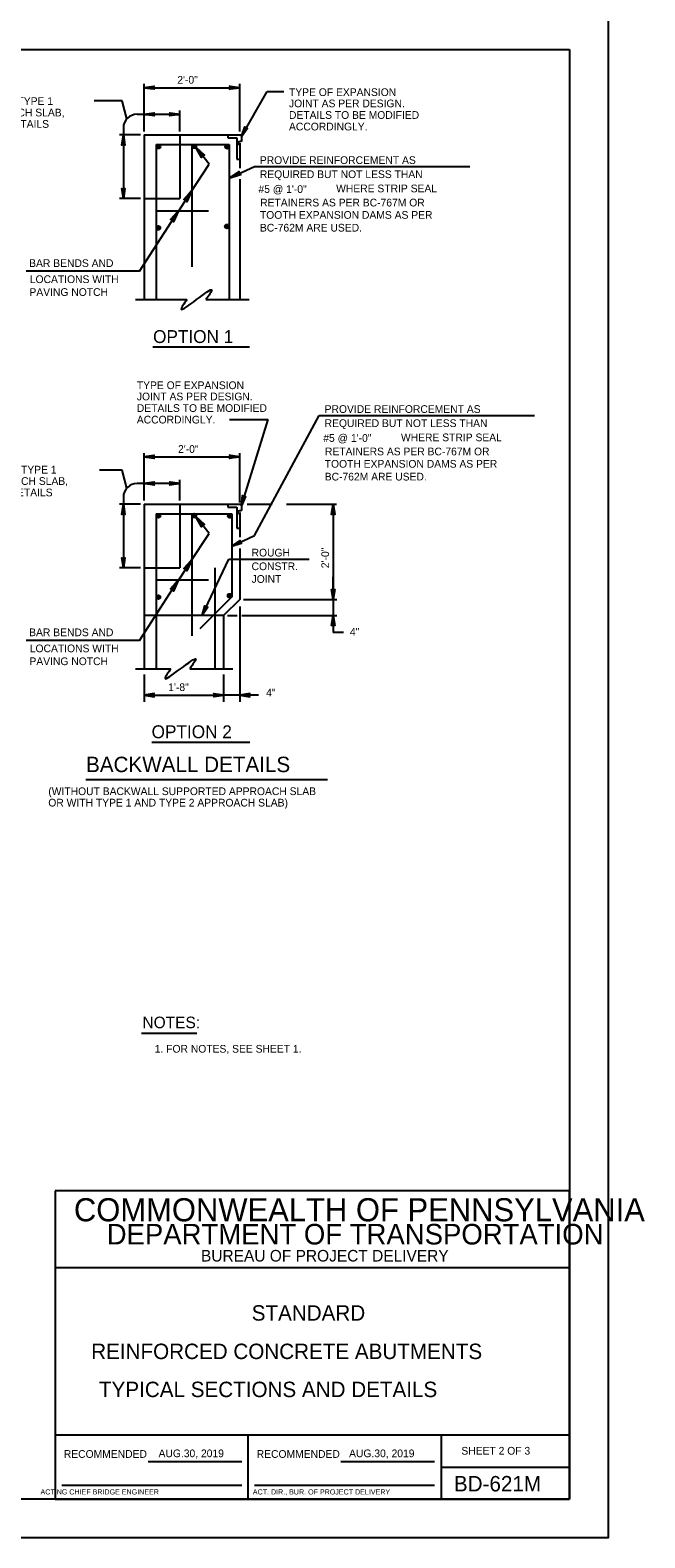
# Model space of a CAD drawing. Extents: x 235 to 2276, y 116 to 1308.
# Drawn here: x 1196 to 1435, y 116 to 703 of the extents above; entities that cross this region are included whole.
import ezdxf

# ---------------------------------------------------------------- set-up
doc = ezdxf.new("R2010")
doc.units = 0
doc.layers.add('1', color=7, linetype='Continuous')
doc.layers.add('PLT-BNDY', color=7, linetype='Continuous')

msp = doc.modelspace()

# ---------------------------------------------------------------- linework, layer by layer
at = {"layer": '1'}
for p, q in [((619.42, 695.41), (1405.42, 695.41)), ((1405.42, 695.41), (1405.42, 131.41)), ((1240.02, 663.53), (1240.02, 682.03)), ((1240.02, 680.53), (1277.14, 680.53)), ((1277.14, 663.53), (1277.14, 682.03)), ((1231.39, 675.4), (1220.58, 675.4)), ((1233.27, 668.4), (1231.39, 675.4)), ((1277.77, 661.53), (1287.77, 679.04)), ((1287.77, 679.04), (1294.23, 679.04)), ((1240.52, 670.15), (1237.27, 670.15)), ((1253.89, 670.15), (1240.02, 670.15)), ((1253.89, 663.53), (1253.89, 671.65)), ((1231.89, 664.9), (1231.89, 660.53)), ((1238.52, 662.15), (1230.39, 662.15)), ((1231.89, 662.15), (1231.89, 637.4)), ((1240.02, 662.15), (1240.02, 598.15)), ((1240.02, 662.15), (1277.77, 662.15)), ((1244.64, 658.4), (1244.64, 598.15)), ((1244.64, 658.4), (1273.08, 658.4)), ((1253.89, 662.15), (1253.89, 637.4)), ((1258.52, 658.4), (1258.52, 610.9)), ((1265.27, 650.78), (1259.89, 657.53)), ((1272.52, 662.15), (1272.52, 661.03)), ((1272.52, 661.03), (1276.02, 661.03)), ((1273.08, 658.4), (1273.08, 598.15)), ((1276.02, 661.03), (1276.02, 652.78)), ((1277.14, 658.9), (1277.14, 649.28)), ((1277.77, 662.15), (1277.77, 659.65)), ((1276.02, 652.78), (1277.14, 652.78)), ((1257.89, 639.53), (1265.27, 650.78)), ((1273.08, 645.28), (1282.89, 649.9)), ((1282.89, 649.9), (1366.6, 649.9)), ((1252.77, 631.65), (1258.52, 640.53)), ((1277.14, 644.9), (1277.14, 598.15)), ((1238.52, 637.4), (1230.39, 637.4)), ((1240.02, 637.4), (1253.89, 637.4)), ((1238.14, 609.15), (1253.39, 632.65)), ((1244.64, 632.65), (1265.02, 632.65)), ((1238.14, 609.15), (1194.14, 609.15)), ((1236.64, 598.15), (1256.64, 598.15)), ((1264.02, 598.15), (1280.77, 598.15)), ((1243.32, 579.68), (1280.9, 579.68)), ((1273.14, 551.41), (1288.14, 551.41)), ((1277.77, 517.91), (1288.14, 551.41)), ((1282.89, 506.28), (1308.08, 553.06)), ((1308.08, 553.06), (1391.8, 553.06)), ((1240.02, 519.91), (1240.02, 538.41)), ((1240.02, 536.91), (1277.14, 536.91)), ((1277.14, 519.16), (1277.14, 538.41)), ((1231.39, 531.78), (1222.64, 531.78)), ((1233.27, 524.78), (1231.39, 531.78)), ((1253.89, 519.91), (1253.89, 528.03)), ((1240.52, 526.53), (1237.27, 526.53)), ((1253.89, 526.53), (1240.02, 526.53)), ((1238.52, 518.53), (1230.39, 518.53)), ((1231.89, 521.28), (1231.89, 516.91)), ((1231.89, 518.53), (1231.89, 493.78)), ((1240.02, 518.53), (1240.02, 454.53)), ((1240.02, 518.53), (1277.77, 518.53)), ((1253.89, 518.53), (1253.89, 493.78)), ((1272.52, 518.53), (1272.52, 517.41)), ((1272.52, 517.41), (1276.02, 517.41)), ((1276.02, 517.41), (1276.02, 509.16)), ((1277.77, 518.53), (1277.77, 516.03)), ((1280.02, 518.53), (1289.77, 518.53)), ((1295.27, 518.53), (1314.77, 518.53)), ((1313.52, 518.53), (1313.52, 481.41)), ((1244.64, 514.78), (1244.64, 454.53)), ((1244.64, 514.78), (1274.14, 514.78)), ((1258.52, 514.78), (1258.52, 467.28)), ((1265.27, 507.16), (1259.89, 513.91)), ((1274.14, 514.78), (1274.14, 482.53)), ((1277.14, 515.28), (1277.14, 505.66)), ((1257.89, 495.91), (1265.27, 507.16)), ((1274.14, 502.16), (1282.89, 506.28)), ((1276.02, 509.16), (1277.14, 509.16)), ((1277.14, 501.28), (1277.14, 481.41)), ((1238.52, 493.78), (1230.39, 493.78)), ((1240.02, 493.78), (1253.89, 493.78)), ((1252.77, 488.03), (1258.52, 496.91)), ((1262.52, 475.16), (1272.89, 497.16)), ((1267.52, 493.78), (1267.52, 454.53)), ((1272.89, 497.16), (1304.14, 497.16)), ((1238.14, 465.53), (1253.39, 489.03)), ((1244.64, 489.03), (1265.02, 489.03)), ((1313.52, 481.41), (1313.52, 490.28)), ((1274.14, 482.53), (1261.64, 470.03)), ((1277.14, 481.41), (1270.89, 475.16)), ((1278.64, 481.41), (1314.89, 481.41)), ((1313.52, 481.41), (1313.52, 468.66)), ((1270.89, 475.16), (1240.02, 475.16)), ((1270.89, 475.16), (1270.89, 454.53)), ((1272.39, 475.16), (1276.14, 475.16)), ((1277.14, 478.7), (1277.14, 441.63)), ((1278.02, 475.16), (1314.89, 475.16)), ((1238.14, 465.53), (1194.14, 465.53)), ((1317.52, 468.66), (1313.52, 468.66)), ((1236.64, 454.53), (1250.39, 454.53)), ((1240.02, 452.28), (1240.02, 441.63)), ((1257.77, 454.53), (1274.52, 454.53)), ((1270.89, 452.28), (1270.89, 441.63)), ((1240.02, 444.18), (1270.89, 444.18)), ((1284.39, 444.18), (1270.89, 444.18)), ((1242.98, 425.96), (1281.08, 425.96)), ((1217.25, 411.43), (1311.22, 411.43)), ((1238.96, 312.73), (1260.49, 312.73)), ((1405.42, 251.41), (1205.42, 251.41)), ((1205.42, 251.41), (1205.42, 131.41)), ((1405.42, 131.41), (1405.42, 251.41)), ((1405.42, 221.41), (1205.42, 221.41)), ((1405.42, 156.41), (1205.42, 156.41)), ((1280.42, 131.41), (1280.42, 156.41)), ((1355.42, 156.41), (1355.42, 131.41)), ((1241.51, 146.13), (1277.92, 146.13)), ((1316.51, 146.13), (1352.92, 146.13)), ((1355.42, 143.91), (1405.42, 143.91)), ((1207.92, 136.91), (1277.92, 136.91)), ((1282.92, 136.91), (1352.92, 136.91)), ((1405.42, 131.41), (619.42, 131.41)), ((1205.42, 131.41), (1405.42, 131.41))]:
    msp.add_line(p, q, dxfattribs=at)
for points in [[(1243.77, 680.03), (1243.64, 680.4), (1240.02, 680.53), (1243.77, 680.03), (1243.89, 679.9), (1240.02, 680.53), (1243.64, 680.78), (1243.77, 681.03), (1240.02, 680.53), (1243.89, 681.15), (1243.77, 681.03)], [(1273.39, 681.03), (1273.52, 680.78), (1277.14, 680.53), (1273.39, 681.03), (1273.14, 681.15), (1277.14, 680.53), (1273.52, 680.4), (1273.39, 680.15), (1277.14, 680.53), (1273.14, 679.9), (1273.39, 680.15)], [(1243.77, 669.78), (1243.64, 670.03), (1240.02, 670.15), (1243.77, 669.78), (1243.89, 669.53), (1240.02, 670.15), (1243.64, 670.4), (1243.77, 670.65), (1240.02, 670.15), (1243.89, 670.78), (1243.77, 670.65)], [(1250.14, 670.65), (1250.27, 670.4), (1253.89, 670.15), (1250.14, 670.65), (1250.02, 670.78), (1253.89, 670.15), (1250.27, 670.03), (1250.14, 669.78), (1253.89, 670.15), (1250.02, 669.53), (1250.14, 669.78)], [(1279.99, 664.62), (1279.6, 664.58), (1277.77, 661.53), (1279.99, 664.62), (1280.14, 664.71), (1277.77, 661.53), (1279.26, 664.78), (1279.19, 665.05), (1277.77, 661.53), (1279.12, 665.32), (1279.19, 665.05)], [(1231.39, 658.4), (1231.77, 658.53), (1231.89, 662.15), (1231.39, 658.4), (1231.27, 658.15), (1231.89, 662.15), (1232.14, 658.53), (1232.39, 658.4), (1231.89, 662.15), (1232.52, 658.15), (1232.39, 658.4)], [(1262.29, 653.63), (1262.44, 653.93), (1259.89, 657.53), (1262.29, 653.63), (1262.29, 653.33), (1259.89, 657.53), (1262.74, 654.23), (1263.19, 654.38), (1259.89, 657.53), (1263.49, 654.23), (1263.19, 654.38)], [(1277.43, 646.78), (1277.13, 646.93), (1273.08, 645.28), (1277.43, 646.78), (1277.58, 646.63), (1273.08, 645.28), (1276.83, 647.38), (1276.83, 647.68), (1273.08, 645.28), (1276.98, 647.98), (1276.83, 647.68)], [(1232.39, 641.15), (1232.14, 640.9), (1231.89, 637.4), (1232.39, 641.15), (1232.52, 641.28), (1231.89, 637.4), (1231.77, 640.9), (1231.52, 641.03), (1231.89, 637.4), (1231.27, 641.28), (1231.52, 641.03)], [(1255.67, 637.08), (1255.97, 637.08), (1258.52, 640.53), (1255.67, 637.08), (1255.37, 637.08), (1258.52, 640.53), (1256.42, 636.78), (1256.57, 636.48), (1258.52, 640.53), (1256.57, 636.18), (1256.57, 636.48)], [(1250.54, 629.2), (1250.84, 629.2), (1253.39, 632.65), (1250.54, 629.2), (1250.24, 629.2), (1253.39, 632.65), (1251.29, 629.05), (1251.44, 628.6), (1253.39, 632.65), (1251.44, 628.3), (1251.44, 628.6)], [(1243.77, 536.41), (1243.64, 536.78), (1240.02, 536.91), (1243.77, 536.41), (1243.89, 536.28), (1240.02, 536.91), (1243.64, 537.16), (1243.77, 537.41), (1240.02, 536.91), (1243.89, 537.53), (1243.77, 537.41)], [(1273.39, 537.41), (1273.52, 537.16), (1277.14, 536.91), (1273.39, 537.41), (1273.14, 537.53), (1277.14, 536.91), (1273.52, 536.78), (1273.39, 536.53), (1277.14, 536.91), (1273.14, 536.28), (1273.39, 536.53)], [(1243.77, 526.16), (1243.64, 526.41), (1240.02, 526.53), (1243.77, 526.16), (1243.89, 525.91), (1240.02, 526.53), (1243.64, 526.78), (1243.77, 527.03), (1240.02, 526.53), (1243.89, 527.16), (1243.77, 527.03)], [(1250.14, 527.03), (1250.27, 526.78), (1253.89, 526.53), (1250.14, 527.03), (1250.02, 527.16), (1253.89, 526.53), (1250.27, 526.41), (1250.14, 526.16), (1253.89, 526.53), (1250.02, 525.91), (1250.14, 526.16)], [(1231.39, 514.78), (1231.77, 514.91), (1231.89, 518.53), (1231.39, 514.78), (1231.27, 514.53), (1231.89, 518.53), (1232.14, 514.91), (1232.39, 514.78), (1231.89, 518.53), (1232.52, 514.53), (1232.39, 514.78)], [(1279.27, 521.41), (1278.89, 521.28), (1277.77, 517.91), (1279.27, 521.41), (1279.39, 521.53), (1277.77, 517.91), (1278.52, 521.41), (1278.39, 521.66), (1277.77, 517.91), (1278.27, 521.91), (1278.39, 521.66)], [(1313.02, 514.78), (1313.27, 514.91), (1313.52, 518.53), (1313.02, 514.78), (1312.89, 514.53), (1313.52, 518.53), (1313.64, 514.91), (1314.02, 514.78), (1313.52, 518.53), (1314.14, 514.53), (1314.02, 514.78)], [(1262.29, 510.01), (1262.44, 510.31), (1259.89, 513.91), (1262.29, 510.01), (1262.29, 509.71), (1259.89, 513.91), (1262.74, 510.61), (1263.19, 510.76), (1259.89, 513.91), (1263.49, 510.61), (1263.19, 510.76)], [(1277.64, 503.41), (1277.39, 503.53), (1274.02, 502.16), (1277.64, 503.41), (1277.77, 503.28), (1274.02, 502.16), (1277.14, 503.91), (1277.14, 504.16), (1274.02, 502.16), (1277.27, 504.41), (1277.14, 504.16)], [(1232.39, 497.53), (1232.14, 497.28), (1231.89, 493.78), (1232.39, 497.53), (1232.52, 497.66), (1231.89, 493.78), (1231.77, 497.28), (1231.52, 497.41), (1231.89, 493.78), (1231.27, 497.66), (1231.52, 497.41)], [(1255.67, 493.46), (1255.97, 493.46), (1258.52, 496.91), (1255.67, 493.46), (1255.37, 493.46), (1258.52, 496.91), (1256.42, 493.16), (1256.57, 492.86), (1258.52, 496.91), (1256.57, 492.56), (1256.57, 492.86)], [(1250.54, 485.58), (1250.84, 485.58), (1253.39, 489.03), (1250.54, 485.58), (1250.24, 485.58), (1253.39, 489.03), (1251.29, 485.43), (1251.44, 484.98), (1253.39, 489.03), (1251.44, 484.68), (1251.44, 484.98)], [(1314.02, 485.16), (1313.77, 484.91), (1313.52, 481.41), (1314.02, 485.16), (1314.14, 485.28), (1313.52, 481.41), (1313.39, 484.91), (1313.02, 485.03), (1313.52, 481.41), (1312.89, 485.28), (1313.02, 485.03)], [(1264.52, 478.41), (1264.14, 478.28), (1262.52, 475.16), (1264.52, 478.41), (1264.77, 478.41), (1262.52, 475.16), (1263.89, 478.53), (1263.64, 478.78), (1262.52, 475.16), (1263.64, 479.03), (1263.64, 478.78)], [(1313.02, 471.41), (1313.27, 471.53), (1313.52, 475.16), (1313.02, 471.41), (1312.89, 471.28), (1313.52, 475.16), (1313.64, 471.53), (1314.02, 471.41), (1313.52, 475.16), (1314.14, 471.28), (1314.02, 471.41)], [(1243.77, 444.68), (1243.52, 444.43), (1240.02, 444.18), (1243.77, 444.68), (1243.89, 444.81), (1240.02, 444.18), (1243.52, 444.06), (1243.64, 443.68), (1240.02, 444.18), (1243.89, 443.56), (1243.64, 443.68)], [(1267.14, 444.68), (1267.39, 444.43), (1270.89, 444.18), (1267.14, 444.68), (1267.02, 444.81), (1270.89, 444.18), (1267.39, 444.06), (1267.27, 443.68), (1270.89, 444.18), (1267.02, 443.56), (1267.27, 443.68)], [(1280.89, 444.68), (1280.64, 444.43), (1277.14, 444.18), (1280.89, 444.68), (1281.02, 444.81), (1277.14, 444.18), (1280.64, 444.06), (1280.77, 443.68), (1277.14, 444.18), (1281.02, 443.56), (1280.77, 443.68)]]:
    msp.add_lwpolyline(points, dxfattribs=at)
for centre, radius in [((1245.56, 657.61), 0.763), ((1245.56, 657.61), 0.545), ((1245.56, 657.61), 0.298), ((1245.56, 657.61), 0.15), ((1245.56, 657.61), 0.0644), ((1259.46, 657.72), 0.763), ((1259.46, 657.72), 0.545), ((1259.46, 657.72), 0.298), ((1259.46, 657.72), 0.15), ((1259.46, 657.72), 0.0644), ((1272.26, 657.56), 0.763), ((1272.26, 657.56), 0.545), ((1272.26, 657.56), 0.298), ((1272.26, 657.56), 0.15), ((1272.26, 657.56), 0.0644), ((1245.51, 625.98), 0.763), ((1245.51, 625.98), 0.545), ((1245.51, 625.98), 0.298), ((1245.51, 625.98), 0.15), ((1245.51, 625.98), 0.0644), ((1272.18, 626.56), 0.763), ((1272.18, 626.56), 0.545), ((1272.18, 626.56), 0.298), ((1272.18, 626.56), 0.15), ((1272.18, 626.56), 0.0644), ((1245.56, 513.98), 0.763), ((1245.56, 513.98), 0.545), ((1245.56, 513.98), 0.298), ((1245.56, 513.98), 0.15), ((1245.56, 513.98), 0.0644), ((1259.46, 514.1), 0.763), ((1259.46, 514.1), 0.545), ((1259.46, 514.1), 0.298), ((1259.46, 514.1), 0.15), ((1259.46, 514.1), 0.0644), ((1273.32, 513.94), 0.763), ((1273.32, 513.94), 0.545), ((1273.32, 513.94), 0.298), ((1273.32, 513.94), 0.15), ((1273.32, 513.94), 0.0644), ((1245.51, 482.35), 0.763), ((1245.51, 482.35), 0.545), ((1245.51, 482.35), 0.298), ((1245.51, 482.35), 0.15), ((1245.51, 482.35), 0.0644), ((1273.24, 482.94), 0.763), ((1273.24, 482.94), 0.545), ((1273.24, 482.94), 0.298), ((1273.24, 482.94), 0.15), ((1273.24, 482.94), 0.0644)]:
    msp.add_circle(centre, radius, dxfattribs=at)
for centre in [(1237.22, 664.88), (1237.22, 521.26)]:
    msp.add_arc(centre, 5.31, 90, 180, dxfattribs=at)
for points in [[(1277.77, 659.65), (1277.02, 659.53), (1276.52, 659.28), (1276.64, 658.53), (1277.14, 658.9)], [(1256.64, 598.15), (1254.39, 594.4), (1266.27, 601.78), (1264.02, 598.15)], [(1277.77, 516.03), (1277.02, 515.91), (1276.52, 515.66), (1276.64, 514.91), (1277.14, 515.28)], [(1250.39, 454.53), (1248.14, 450.78), (1260.02, 458.16), (1257.77, 454.53)]]:
    msp.add_spline(points, degree=3, dxfattribs=at)
at = {"layer": 'PLT-BNDY'}
msp.add_lwpolyline([(579.42, 710.41), (1420.42, 710.41), (1420.42, 116.41), (579.42, 116.41)], close=True, dxfattribs=at)

# ---------------------------------------------------------------- texts
at = {"layer": '1'}
for s, height, p in [('2\'-0"', 3, (1252.87, 682.09)), ('PAVING NOTCH FOR TYPE 1', 3, (1149.5, 673.8)), ('JOINT AS PER DESIGN.', 3, (1296.3, 672.91)), ('TYPE OF EXPANSION', 3, (1296.3, 677.29)), ('AND TYPE 2 APPROACH SLAB,', 3, (1149.5, 669.36)), ('DETAILS TO BE MODIFIED', 3, (1296.3, 668.41)), ('SEE BD-628M FOR DETAILS', 3, (1149.5, 664.92)), ('ACCORDINGLY.', 3, (1296.3, 663.91)), ('PROVIDE REINFORCEMENT AS', 3, (1284.97, 650.85)), ('REQUIRED BUT NOT LESS THAN', 3, (1284.97, 645.37)), ('#5 @ 1\'-0"', 3, (1284.43, 639.59)), (' WHERE STRIP SEAL', 3, (1313.52, 639.84)), ('RETAINERS AS PER BC-767M OR', 3, (1285.09, 634.34)), ('TOOTH EXPANSION DAMS AS PER', 3, (1285, 629.54)), ('BC-762M ARE USED.', 3, (1285, 624.57)), ('BAR BENDS AND', 3, (1195.27, 610.78)), ('LOCATIONS WITH', 3, (1195.52, 604.53)), ('PAVING NOTCH', 3, (1195.39, 599.53)), ('OPTION 1', 5, (1243.45, 581.21)), ('TYPE OF EXPANSION', 3, (1237.14, 563.28)), ('JOINT AS PER DESIGN.', 3, (1237.14, 558.91)), ('DETAILS TO BE MODIFIED', 3, (1237.14, 554.41)), ('ACCORDINGLY.', 3, (1237.14, 549.91)), ('PROVIDE REINFORCEMENT AS', 3, (1310.16, 554.02)), ('REQUIRED BUT NOT LESS THAN', 3, (1310.16, 548.53)), ('#5 @ 1\'-0"', 3, (1309.62, 542.76)), (' WHERE STRIP SEAL', 3, (1338.71, 543)), ('2\'-0"', 3, (1253.15, 538.47)), ('RETAINERS AS PER BC-767M OR', 3, (1310.28, 537.51)), ('TOOTH EXPANSION DAMS AS PER', 3, (1310.19, 532.71)), ('AND TYPE 2 APPROACH SLAB,', 3, (1150.87, 526.01)), ('PAVING NOTCH FOR TYPE 1', 3, (1150.87, 530.45)), ('BC-762M ARE USED.', 3, (1310.19, 527.73)), ('SEE BD-628M FOR DETAILS', 3, (1150.87, 521.57)), ('ROUGH', 3, (1281.75, 498.17)), ('CONSTR. ', 3, (1281.75, 492.86)), ('JOINT', 3, (1281.75, 487.92)), ('BAR BENDS AND', 3, (1195.27, 467.16)), ('4"', 3, (1319.99, 467.34)), ('LOCATIONS WITH', 3, (1195.52, 460.91)), ('PAVING NOTCH', 3, (1195.39, 455.91)), ('1\'-8"', 3, (1249.34, 445.82)), ('4"', 3, (1287.43, 443.72)), ('OPTION 2', 5, (1242.88, 427.49)), ('BACKWALL DETAILS', 6, (1217.39, 414.28)), ('(WITHOUT BACKWALL SUPPORTED APPROACH SLAB', 3, (1202.72, 405.35)), ('OR WITH TYPE 1 AND TYPE 2 APPROACH SLAB)', 3, (1202.72, 400.91)), ('NOTES:', 4.5, (1239.33, 314.67)), ('1. FOR NOTES, SEE SHEET 1.', 3, (1244.09, 305.16)), ('COMMONWEALTH OF PENNSYLVANIA', 9, (1212.67, 239.54)), ('DEPARTMENT OF TRANSPORTATION', 8.0002, (1225.42, 230.54)), ('BUREAU OF PROJECT DELIVERY', 4.5, (1262.08, 223.91)), ('STANDARD', 6, (1281.8, 200.91)), ('REINFORCED CONCRETE ABUTMENTS', 6, (1219.4, 185.96)), ('TYPICAL SECTIONS AND DETAILS', 6, (1222.42, 171.16)), ('RECOMMENDED', 3, (1208.75, 147.54)), ('AUG.30, 2019', 3, (1245.58, 147.78)), ('RECOMMENDED', 3, (1283.75, 147.54)), ('AUG.30, 2019', 3, (1319.67, 147.78)), ('SHEET 2 OF 3', 3, (1363.33, 148.79)), ('ACT. DIR., BUR. OF PROJECT DELIVERY', 2.0002, (1282.24, 133.29)), ('BD-621M', 6, (1360.42, 134.48))]:
    msp.add_text(s, height=height, dxfattribs=at).set_placement(p)
for s, height, rotation, p in [('2\'-0"', 3, 90, (1311.87, 493.62)), ('       ACTING CHIEF BRIDGE ENGINEER', 2.0002, 360, (1194.31, 133.29))]:
    msp.add_text(s, height=height, rotation=rotation, dxfattribs=at).set_placement(p)

doc.saveas('drawing.dxf')
